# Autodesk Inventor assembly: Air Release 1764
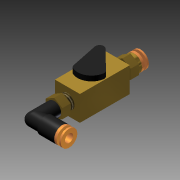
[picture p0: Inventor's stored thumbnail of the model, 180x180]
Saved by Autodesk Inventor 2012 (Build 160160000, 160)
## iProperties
Created: 2010-02
Part Number: Air Release 1764
Document SubType Name: Assembly
Designer: jgehrig
Author: jgehrig
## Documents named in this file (5)
- R:\CAD Archives\Pneumatics_1764\Air_Release_1764\Air_Release_1764.iam
- R:\CAD Archives\Pneumatics_1764\Air_Release_1764\Air_Release_Base_1764.ipt
- R:\CAD Archives\Pneumatics_1764\Air_Release_1764\Knob_1764.ipt
- R:\CAD Archives\Pneumatics_1764\Air_Release_1764\Pneumatic_Screw_1764\Pneumatic_Screw_1764.iam
- R:\CAD Archives\Pneumatics_1764\Air_Release_1764\Pneumatics_Bend_Piece_1764\Pneumatic_Bend_Piece_1764.iam
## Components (4 placed, 4 different names)
1. Air_Release_Base_1764:1 — Insert:1, Insert:2, Insert:3, Angle:1
2. Knob_1764:1 — Insert:1
3. Pneumatic_Screw_1764:1 [sub-assembly] — Insert:2
4. Pneumatic_Bend_Piece_1764:1 [sub-assembly] — Insert:3, Angle:1
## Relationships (4: Insert 3, Angle 1)
- Insert:1: Air_Release_Base_1764:1 ↔ Knob_1764:1
- Insert:2: Air_Release_Base_1764:1 ↔ Pneumatic_Screw_1764:1
- Insert:3: Air_Release_Base_1764:1 ↔ Pneumatic_Bend_Piece_1764:1
- Angle:1: Air_Release_Base_1764:1 ↔ Pneumatic_Bend_Piece_1764:1
